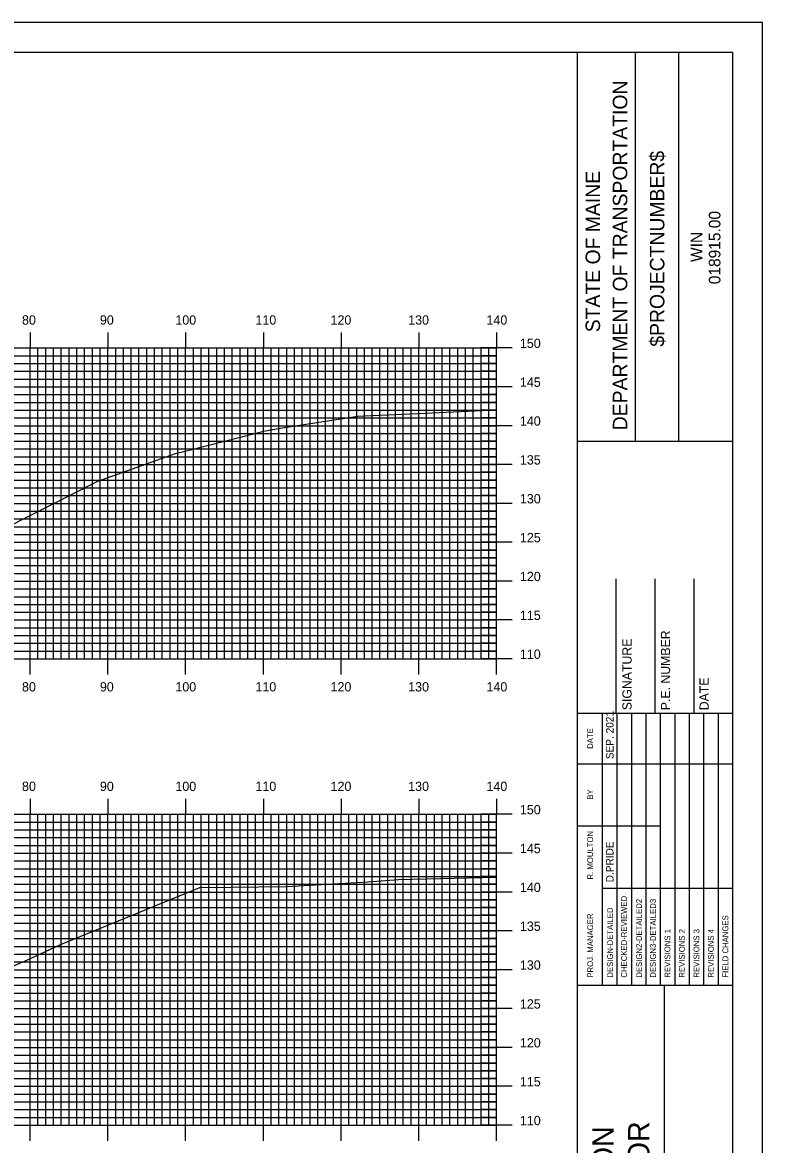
# Model space of a CAD drawing. Extents: x 853721 to 854064, y 364661 to 364881.
# Drawn here: x 853965.8 to 854061, y 364736.9 to 364881.3 of the extents above; entities that cross this region are included whole.
import ezdxf

# ---------------------------------------------------------------- set-up
doc = ezdxf.new("R2010")
doc.units = 0
for name, color, linetype in [('BORDER', 7, 'Continuous'), ('H_V ANNOTATION', 7, 'Continuous'), ('MAJOR', 7, 'Continuous'), ('MINOR', 7, 'Continuous'), ('PLOT BOUNDARY', 7, 'Continuous'), ('S_Roadway_Centerline', 7, 'Continuous')]:
    doc.layers.add(name, color=color, linetype=linetype)

msp = doc.modelspace()

# ---------------------------------------------------------------- linework, layer by layer
at = {"layer": 'BORDER'}
for p, q in [((854037.21, 364667.37), (854037.21, 364877.37)), ((854044.66, 364827.36), (854044.66, 364877.36)), ((854050.25, 364827.36), (854050.25, 364877.36)), ((854037.21, 364827.36), (854057.21, 364827.36)), ((854042.21, 364792.38), (854042.21, 364809.67)), ((854047.21, 364792.38), (854047.21, 364809.67)), ((854052.21, 364792.38), (854052.21, 364809.67)), ((854037.21, 364792.38), (854057.21, 364792.38)), ((854037.21, 364757.38), (854057.21, 364757.38)), ((854048.39, 364687.38), (854048.39, 364757.38))]:
    msp.add_line(p, q, dxfattribs=at)
msp.add_lwpolyline([(853737.21, 364667.37), (854057.21, 364667.37), (854057.21, 364877.37), (853737.21, 364877.37)], close=True, dxfattribs=at)
for points in [[(854040.44, 364785.88), (854040.44, 364792.38)], [(854042.3, 364757.38), (854042.3, 364792.38)], [(854044.17, 364792.38), (854044.17, 364757.38)], [(854046.03, 364757.38), (854046.03, 364792.38)], [(854047.89, 364757.38), (854047.89, 364792.38)], [(854049.76, 364757.38), (854049.76, 364792.38)], [(854051.62, 364757.38), (854051.62, 364792.38)], [(854053.48, 364757.38), (854053.48, 364792.38)], [(854055.35, 364757.38), (854055.35, 364792.38)], [(854040.44, 364757.38), (854040.44, 364790.96)], [(854037.21, 364785.88), (854057.21, 364785.88)], [(854037.21, 364777.88), (854040.44, 364777.88)], [(854040.44, 364777.88), (854047.89, 364777.88)], [(854040.44, 364769.88), (854057.21, 364769.88)]]:
    msp.add_lwpolyline(points, dxfattribs=at)
at = {"layer": 'MAJOR'}
for p, q in [((853966.81, 364841.37), (853966.81, 364839.37)), ((853976.81, 364841.37), (853976.81, 364839.37)), ((853986.81, 364841.37), (853986.81, 364839.37)), ((853996.81, 364841.37), (853996.81, 364839.37)), ((854006.81, 364841.37), (854006.81, 364839.37)), ((854016.81, 364841.37), (854016.81, 364839.37)), ((854026.81, 364841.37), (854026.81, 364839.37)), ((853746.81, 364839.37), (854026.81, 364839.37)), ((853746.81, 364839.37), (854026.81, 364839.37)), ((853966.81, 364799.37), (853966.81, 364839.37)), ((853976.81, 364799.37), (853976.81, 364839.37)), ((853986.81, 364799.37), (853986.81, 364839.37)), ((853996.81, 364799.37), (853996.81, 364839.37)), ((854006.81, 364799.37), (854006.81, 364839.37)), ((854016.81, 364799.37), (854016.81, 364839.37)), ((854028.81, 364839.37), (854024.8, 364839.37)), ((854026.81, 364799.37), (854026.81, 364839.37)), ((854026.81, 364799.37), (854026.81, 364839.37)), ((853746.81, 364834.37), (854026.81, 364834.37)), ((854028.81, 364834.37), (854024.8, 364834.37)), ((853746.81, 364829.37), (854026.81, 364829.37)), ((854028.81, 364829.37), (854024.8, 364829.37)), ((853746.81, 364824.37), (854026.81, 364824.37)), ((854028.81, 364824.37), (854024.8, 364824.37)), ((853746.81, 364819.37), (854026.81, 364819.37)), ((854028.81, 364819.37), (854024.8, 364819.37)), ((853746.81, 364814.37), (854026.81, 364814.37)), ((854028.81, 364814.37), (854024.8, 364814.37)), ((853746.81, 364809.37), (854026.81, 364809.37)), ((854028.81, 364809.37), (854024.8, 364809.37)), ((853746.81, 364804.37), (854026.81, 364804.37)), ((854028.81, 364804.37), (854024.8, 364804.37)), ((853746.81, 364799.37), (854026.81, 364799.37)), ((853746.81, 364799.37), (854026.81, 364799.37)), ((853966.81, 364797.37), (853966.81, 364799.37)), ((853976.81, 364797.37), (853976.81, 364799.37)), ((853986.81, 364797.37), (853986.81, 364799.37)), ((853996.81, 364797.37), (853996.81, 364799.37)), ((854006.81, 364797.37), (854006.81, 364799.37)), ((854016.81, 364797.37), (854016.81, 364799.37)), ((854028.81, 364799.37), (854024.8, 364799.37)), ((854026.81, 364797.37), (854026.81, 364799.37)), ((853966.81, 364781.37), (853966.81, 364779.37)), ((853976.81, 364781.37), (853976.81, 364779.37)), ((853986.81, 364781.37), (853986.81, 364779.37)), ((853996.81, 364781.37), (853996.81, 364779.37)), ((854006.81, 364781.37), (854006.81, 364779.37)), ((854016.81, 364781.37), (854016.81, 364779.37)), ((854026.81, 364781.37), (854026.81, 364779.37)), ((853746.81, 364779.37), (854026.81, 364779.37)), ((853746.81, 364779.37), (854026.81, 364779.37)), ((853966.81, 364739.37), (853966.81, 364779.37)), ((853976.81, 364739.37), (853976.81, 364779.37)), ((853986.81, 364739.37), (853986.81, 364779.37)), ((853996.81, 364739.37), (853996.81, 364779.37)), ((854006.81, 364739.37), (854006.81, 364779.37)), ((854016.81, 364739.37), (854016.81, 364779.37)), ((854028.81, 364779.37), (854024.8, 364779.37)), ((854026.81, 364739.37), (854026.81, 364779.37)), ((854026.81, 364739.37), (854026.81, 364779.37)), ((853746.81, 364774.37), (854026.81, 364774.37)), ((854028.81, 364774.37), (854024.8, 364774.37)), ((853746.81, 364769.37), (854026.81, 364769.37)), ((854028.81, 364769.37), (854024.8, 364769.37)), ((853746.81, 364764.37), (854026.81, 364764.37)), ((854028.81, 364764.37), (854024.8, 364764.37)), ((853746.81, 364759.37), (854026.81, 364759.37)), ((854028.81, 364759.37), (854024.8, 364759.37)), ((853746.81, 364754.37), (854026.81, 364754.37)), ((854028.81, 364754.37), (854024.8, 364754.37)), ((853746.81, 364749.37), (854026.81, 364749.37)), ((854028.81, 364749.37), (854024.8, 364749.37)), ((853746.81, 364744.37), (854026.81, 364744.37)), ((854028.81, 364744.37), (854024.8, 364744.37)), ((853746.81, 364739.37), (854026.81, 364739.37)), ((853746.81, 364739.37), (854026.81, 364739.37)), ((853966.81, 364737.37), (853966.81, 364739.37)), ((853976.81, 364737.37), (853976.81, 364739.37)), ((853986.81, 364737.37), (853986.81, 364739.37)), ((853996.81, 364737.37), (853996.81, 364739.37)), ((854006.81, 364737.37), (854006.81, 364739.37)), ((854016.81, 364737.37), (854016.81, 364739.37)), ((854028.81, 364739.37), (854024.8, 364739.37)), ((854026.81, 364737.37), (854026.81, 364739.37))]:
    msp.add_line(p, q, dxfattribs=at)
at = {"layer": 'MINOR'}
for p, q in [((853746.81, 364838.37), (854026.81, 364838.37)), ((853967.81, 364799.37), (853967.81, 364839.37)), ((853968.81, 364799.37), (853968.81, 364839.37)), ((853969.81, 364799.37), (853969.81, 364839.37)), ((853970.81, 364799.37), (853970.81, 364839.37)), ((853971.81, 364799.37), (853971.81, 364839.37)), ((853972.81, 364799.37), (853972.81, 364839.37)), ((853973.81, 364799.37), (853973.81, 364839.37)), ((853974.81, 364799.37), (853974.81, 364839.37)), ((853975.81, 364799.37), (853975.81, 364839.37)), ((853977.81, 364799.37), (853977.81, 364839.37)), ((853978.81, 364799.37), (853978.81, 364839.37)), ((853979.81, 364799.37), (853979.81, 364839.37)), ((853980.81, 364799.37), (853980.81, 364839.37)), ((853981.81, 364799.37), (853981.81, 364839.37)), ((853982.81, 364799.37), (853982.81, 364839.37)), ((853983.81, 364799.37), (853983.81, 364839.37)), ((853984.81, 364799.37), (853984.81, 364839.37)), ((853985.81, 364799.37), (853985.81, 364839.37)), ((853987.81, 364799.37), (853987.81, 364839.37)), ((853988.81, 364799.37), (853988.81, 364839.37)), ((853989.81, 364799.37), (853989.81, 364839.37)), ((853990.81, 364799.37), (853990.81, 364839.37)), ((853991.81, 364799.37), (853991.81, 364839.37)), ((853992.81, 364799.37), (853992.81, 364839.37)), ((853993.81, 364799.37), (853993.81, 364839.37)), ((853994.81, 364799.37), (853994.81, 364839.37)), ((853995.81, 364799.37), (853995.81, 364839.37)), ((853997.81, 364799.37), (853997.81, 364839.37)), ((853998.81, 364799.37), (853998.81, 364839.37)), ((853999.81, 364799.37), (853999.81, 364839.37)), ((854000.81, 364799.37), (854000.81, 364839.37)), ((854001.81, 364799.37), (854001.81, 364839.37)), ((854002.81, 364799.37), (854002.81, 364839.37)), ((854003.81, 364799.37), (854003.81, 364839.37)), ((854004.81, 364799.37), (854004.81, 364839.37)), ((854005.81, 364799.37), (854005.81, 364839.37)), ((854007.81, 364799.37), (854007.81, 364839.37)), ((854008.81, 364799.37), (854008.81, 364839.37)), ((854009.81, 364799.37), (854009.81, 364839.37)), ((854010.81, 364799.37), (854010.81, 364839.37)), ((854011.81, 364799.37), (854011.81, 364839.37)), ((854012.81, 364799.37), (854012.81, 364839.37)), ((854013.81, 364799.37), (854013.81, 364839.37)), ((854014.81, 364799.37), (854014.81, 364839.37)), ((854015.81, 364799.37), (854015.81, 364839.37)), ((854017.81, 364799.37), (854017.81, 364839.37)), ((854018.81, 364799.37), (854018.81, 364839.37)), ((854019.81, 364799.37), (854019.81, 364839.37)), ((854020.81, 364799.37), (854020.81, 364839.37)), ((854021.81, 364799.37), (854021.81, 364839.37)), ((854022.81, 364799.37), (854022.81, 364839.37)), ((854023.81, 364799.37), (854023.81, 364839.37)), ((854026.81, 364838.37), (854024.8, 364838.37)), ((854024.81, 364799.37), (854024.81, 364839.37)), ((854025.81, 364799.37), (854025.81, 364839.37)), ((853746.81, 364837.37), (854026.81, 364837.37)), ((854026.81, 364837.37), (854024.8, 364837.37)), ((853746.81, 364836.37), (854026.81, 364836.37)), ((853746.81, 364835.37), (854026.81, 364835.37)), ((854026.81, 364836.37), (854024.8, 364836.37)), ((854026.81, 364835.37), (854024.8, 364835.37)), ((853746.81, 364833.37), (854026.81, 364833.37)), ((853746.81, 364832.37), (854026.81, 364832.37)), ((854026.81, 364833.37), (854024.8, 364833.37)), ((854026.81, 364832.37), (854024.8, 364832.37)), ((853746.81, 364831.37), (854026.81, 364831.37)), ((854026.81, 364831.37), (854024.8, 364831.37)), ((853746.81, 364830.37), (854026.81, 364830.37)), ((854026.81, 364830.37), (854024.8, 364830.37)), ((853746.81, 364828.37), (854026.81, 364828.37)), ((854026.81, 364828.37), (854024.8, 364828.37)), ((853746.81, 364827.37), (854026.81, 364827.37)), ((854026.81, 364827.37), (854024.8, 364827.37)), ((853746.81, 364826.37), (854026.81, 364826.37)), ((853746.81, 364825.37), (854026.81, 364825.37)), ((854026.81, 364826.37), (854024.8, 364826.37)), ((854026.81, 364825.37), (854024.8, 364825.37)), ((853746.81, 364823.37), (854026.81, 364823.37)), ((853746.81, 364822.37), (854026.81, 364822.37)), ((854026.81, 364823.37), (854024.8, 364823.37)), ((854026.81, 364822.37), (854024.8, 364822.37)), ((853746.81, 364821.37), (854026.81, 364821.37)), ((854026.81, 364821.37), (854024.8, 364821.37)), ((853746.81, 364820.37), (854026.81, 364820.37)), ((854026.81, 364820.37), (854024.8, 364820.37)), ((853746.81, 364818.37), (854026.81, 364818.37)), ((854026.81, 364818.37), (854024.8, 364818.37)), ((853746.81, 364817.37), (854026.81, 364817.37)), ((853746.81, 364816.37), (854026.81, 364816.37)), ((854026.81, 364817.37), (854024.8, 364817.37)), ((854026.81, 364816.37), (854024.8, 364816.37)), ((853746.81, 364815.37), (854026.81, 364815.37)), ((854026.81, 364815.37), (854024.8, 364815.37)), ((853746.81, 364813.37), (854026.81, 364813.37)), ((853746.81, 364812.37), (854026.81, 364812.37)), ((854026.81, 364813.37), (854024.8, 364813.37)), ((854026.81, 364812.37), (854024.8, 364812.37)), ((853746.81, 364811.37), (854026.81, 364811.37)), ((854026.81, 364811.37), (854024.8, 364811.37)), ((853746.81, 364810.37), (854026.81, 364810.37)), ((854026.81, 364810.37), (854024.8, 364810.37)), ((853746.81, 364808.37), (854026.81, 364808.37)), ((854026.81, 364808.37), (854024.8, 364808.37)), ((853746.81, 364807.37), (854026.81, 364807.37)), ((853746.81, 364806.37), (854026.81, 364806.37)), ((854026.81, 364807.37), (854024.8, 364807.37)), ((854026.81, 364806.37), (854024.8, 364806.37)), ((853746.81, 364805.37), (854026.81, 364805.37)), ((854026.81, 364805.37), (854024.8, 364805.37)), ((853746.81, 364803.37), (854026.81, 364803.37)), ((854026.81, 364803.37), (854024.8, 364803.37)), ((853746.81, 364802.37), (854026.81, 364802.37)), ((854026.81, 364802.37), (854024.8, 364802.37)), ((853746.81, 364801.37), (854026.81, 364801.37)), ((854026.81, 364801.37), (854024.8, 364801.37)), ((853746.81, 364800.37), (854026.81, 364800.37)), ((854026.81, 364800.37), (854024.8, 364800.37)), ((853967.81, 364739.37), (853967.81, 364779.37)), ((853968.81, 364739.37), (853968.81, 364779.37)), ((853969.81, 364739.37), (853969.81, 364779.37)), ((853970.81, 364739.37), (853970.81, 364779.37)), ((853971.81, 364739.37), (853971.81, 364779.37)), ((853972.81, 364739.37), (853972.81, 364779.37)), ((853973.81, 364739.37), (853973.81, 364779.37)), ((853974.81, 364739.37), (853974.81, 364779.37)), ((853975.81, 364739.37), (853975.81, 364779.37)), ((853977.81, 364739.37), (853977.81, 364779.37)), ((853978.81, 364739.37), (853978.81, 364779.37)), ((853979.81, 364739.37), (853979.81, 364779.37)), ((853980.81, 364739.37), (853980.81, 364779.37)), ((853981.81, 364739.37), (853981.81, 364779.37)), ((853982.81, 364739.37), (853982.81, 364779.37)), ((853983.81, 364739.37), (853983.81, 364779.37)), ((853984.81, 364739.37), (853984.81, 364779.37)), ((853985.81, 364739.37), (853985.81, 364779.37)), ((853987.81, 364739.37), (853987.81, 364779.37)), ((853988.81, 364739.37), (853988.81, 364779.37)), ((853989.81, 364739.37), (853989.81, 364779.37)), ((853990.81, 364739.37), (853990.81, 364779.37)), ((853991.81, 364739.37), (853991.81, 364779.37)), ((853992.81, 364739.37), (853992.81, 364779.37)), ((853993.81, 364739.37), (853993.81, 364779.37)), ((853994.81, 364739.37), (853994.81, 364779.37)), ((853995.81, 364739.37), (853995.81, 364779.37)), ((853997.81, 364739.37), (853997.81, 364779.37)), ((853998.81, 364739.37), (853998.81, 364779.37)), ((853999.81, 364739.37), (853999.81, 364779.37)), ((854000.81, 364739.37), (854000.81, 364779.37)), ((854001.81, 364739.37), (854001.81, 364779.37)), ((854002.81, 364739.37), (854002.81, 364779.37)), ((854003.81, 364739.37), (854003.81, 364779.37)), ((854004.81, 364739.37), (854004.81, 364779.37)), ((854005.81, 364739.37), (854005.81, 364779.37)), ((854007.81, 364739.37), (854007.81, 364779.37)), ((854008.81, 364739.37), (854008.81, 364779.37)), ((854009.81, 364739.37), (854009.81, 364779.37)), ((854010.81, 364739.37), (854010.81, 364779.37)), ((854011.81, 364739.37), (854011.81, 364779.37)), ((854012.81, 364739.37), (854012.81, 364779.37)), ((854013.81, 364739.37), (854013.81, 364779.37)), ((854014.81, 364739.37), (854014.81, 364779.37)), ((854015.81, 364739.37), (854015.81, 364779.37)), ((854017.81, 364739.37), (854017.81, 364779.37)), ((854018.81, 364739.37), (854018.81, 364779.37)), ((854019.81, 364739.37), (854019.81, 364779.37)), ((854020.81, 364739.37), (854020.81, 364779.37)), ((854021.81, 364739.37), (854021.81, 364779.37)), ((854022.81, 364739.37), (854022.81, 364779.37)), ((854023.81, 364739.37), (854023.81, 364779.37)), ((854024.81, 364739.37), (854024.81, 364779.37)), ((854025.81, 364739.37), (854025.81, 364779.37)), ((853746.81, 364778.37), (854026.81, 364778.37)), ((853746.81, 364777.37), (854026.81, 364777.37)), ((854026.81, 364778.37), (854024.8, 364778.37)), ((854026.81, 364777.37), (854024.8, 364777.37)), ((853746.81, 364776.37), (854026.81, 364776.37)), ((854026.81, 364776.37), (854024.8, 364776.37)), ((853746.81, 364775.37), (854026.81, 364775.37)), ((854026.81, 364775.37), (854024.8, 364775.37)), ((853746.81, 364773.37), (854026.81, 364773.37)), ((854026.81, 364773.37), (854024.8, 364773.37)), ((853746.81, 364772.37), (854026.81, 364772.37)), ((854026.81, 364772.37), (854024.8, 364772.37)), ((853746.81, 364771.37), (854026.81, 364771.37)), ((853746.81, 364770.37), (854026.81, 364770.37)), ((854026.81, 364771.37), (854024.8, 364771.37)), ((854026.81, 364770.37), (854024.8, 364770.37)), ((853746.81, 364768.37), (854026.81, 364768.37)), ((853746.81, 364767.37), (854026.81, 364767.37)), ((854026.81, 364768.37), (854024.8, 364768.37)), ((854026.81, 364767.37), (854024.8, 364767.37)), ((853746.81, 364766.37), (854026.81, 364766.37)), ((854026.81, 364766.37), (854024.8, 364766.37)), ((853746.81, 364765.37), (854026.81, 364765.37)), ((854026.81, 364765.37), (854024.8, 364765.37)), ((853746.81, 364763.37), (854026.81, 364763.37)), ((854026.81, 364763.37), (854024.8, 364763.37)), ((853746.81, 364762.37), (854026.81, 364762.37)), ((854026.81, 364762.37), (854024.8, 364762.37)), ((853746.81, 364761.37), (854026.81, 364761.37)), ((853746.81, 364760.37), (854026.81, 364760.37)), ((854026.81, 364761.37), (854024.8, 364761.37)), ((854026.81, 364760.37), (854024.8, 364760.37)), ((853746.81, 364758.37), (854026.81, 364758.37)), ((853746.81, 364757.37), (854026.81, 364757.37)), ((854026.81, 364758.37), (854024.8, 364758.37)), ((854026.81, 364757.37), (854024.8, 364757.37)), ((853746.81, 364756.37), (854026.81, 364756.37)), ((854026.81, 364756.37), (854024.8, 364756.37)), ((853746.81, 364755.37), (854026.81, 364755.37)), ((854026.81, 364755.37), (854024.8, 364755.37)), ((853746.81, 364753.37), (854026.81, 364753.37)), ((854026.81, 364753.37), (854024.8, 364753.37)), ((853746.81, 364752.37), (854026.81, 364752.37)), ((853746.81, 364751.37), (854026.81, 364751.37)), ((854026.81, 364752.37), (854024.8, 364752.37)), ((854026.81, 364751.37), (854024.8, 364751.37)), ((853746.81, 364750.37), (854026.81, 364750.37)), ((854026.81, 364750.37), (854024.8, 364750.37)), ((853746.81, 364748.37), (854026.81, 364748.37)), ((853746.81, 364747.37), (854026.81, 364747.37)), ((854026.81, 364748.37), (854024.8, 364748.37)), ((854026.81, 364747.37), (854024.8, 364747.37)), ((853746.81, 364746.37), (854026.81, 364746.37)), ((854026.81, 364746.37), (854024.8, 364746.37)), ((853746.81, 364745.37), (854026.81, 364745.37)), ((854026.81, 364745.37), (854024.8, 364745.37)), ((853746.81, 364743.37), (854026.81, 364743.37)), ((854026.81, 364743.37), (854024.8, 364743.37)), ((853746.81, 364742.37), (854026.81, 364742.37)), ((853746.81, 364741.37), (854026.81, 364741.37)), ((854026.81, 364742.37), (854024.8, 364742.37)), ((854026.81, 364741.37), (854024.8, 364741.37)), ((853746.81, 364740.37), (854026.81, 364740.37)), ((854026.81, 364740.37), (854024.8, 364740.37))]:
    msp.add_line(p, q, dxfattribs=at)
at = {"layer": 'PLOT BOUNDARY'}
msp.add_lwpolyline([(853721.02, 364661.25), (854061.02, 364661.25), (854061.02, 364881.25), (853721.02, 364881.25)], close=True, dxfattribs=at)
at = {"layer": 'S_Roadway_Centerline'}
for points in [[(853963.69, 364816.23), (853975.51, 364822.23), (853985.5, 364825.77), (853986.92, 364826.15), (853996.85, 364828.67), (853998.97, 364829.07), (854008.97, 364830.6), (854017.58, 364830.98), (854026.81, 364831.41)], [(853955.69, 364756.08), (853966.28, 364760.55), (853970.62, 364762.59), (853988.63, 364769.96), (853992.63, 364770.01), (853999.79, 364770.06), (854010.3, 364770.7), (854014.17, 364770.97), (854026.81, 364771.26)]]:
    msp.add_lwpolyline(points, dxfattribs=at)

# ---------------------------------------------------------------- texts
at = {"layer": 'BORDER'}
for s, height, p in [('DEPARTMENT OF TRANSPORTATION', 1.8635, (854043.62, 364828.78)), ('$PROJECTNUMBER$', 1.8635, (854048.39, 364839.53)), ('STATE OF MAINE', 1.8635, (854040.12, 364841.39)), ('018915.00', 1.491, (854055.6, 364847.57)), ('WIN', 1.491, (854053.28, 364850.43)), ('SIGNATURE', 1.181, (854044.17, 364792.76)), ('P.E. NUMBER', 1.1811, (854049.13, 364792.76)), ('DATE', 1.181, (854054.09, 364792.76)), ('SEP. 2021', 0.969, (854041.85, 364786.47)), ('DATE', 0.743, (854039.22, 364787.79)), ('BY', 0.743, (854039.22, 364781.25)), ('R. MOULTON', 0.745, (854039.22, 364770.98)), ('D.PRIDE', 0.969, (854041.85, 364770.62)), ('CHECKED-REVIEWED', 0.7455, (854043.57, 364758.35)), ('DESIGN-DETAILED', 0.7455, (854041.78, 364758.35)), ('DESIGN2-DETAILED2', 0.7455, (854045.51, 364758.35)), ('DESIGN3-DETAILED3', 0.7455, (854047.3, 364758.35)), ('PROJ. MANAGER', 0.7455, (854039.22, 364758.35)), ('FIELD CHANGES', 0.7455, (854056.61, 364758.35)), ('REVISIONS 1', 0.7455, (854049.16, 364758.35)), ('REVISIONS 2', 0.7455, (854051.02, 364758.35)), ('REVISIONS 3', 0.7455, (854052.89, 364758.35)), ('REVISIONS 4', 0.7455, (854054.75, 364758.35)), ('BREWER TO EDDINGTON', 2.7557, (854041.88, 364693.78)), ('I-395/ROUTE 9 CONNECTOR', 2.7557, (854046.47, 364689.7))]:
    msp.add_text(s, height=height, rotation=90, dxfattribs=at).set_placement(p)
at = {"layer": 'H_V ANNOTATION'}
for s, p in [('80', (853965.76, 364842.37)), ('90', (853975.78, 364842.37)), ('100', (853985.49, 364842.37)), ('110', (853995.79, 364842.37)), ('120', (854005.45, 364842.37)), ('130', (854015.44, 364842.37)), ('140', (854025.51, 364842.37)), ('150', (854029.81, 364839.37)), ('145', (854029.81, 364834.37)), ('140', (854029.81, 364829.37)), ('135', (854029.81, 364824.37)), ('130', (854029.81, 364819.37)), ('125', (854029.81, 364814.37)), ('120', (854029.81, 364809.37)), ('115', (854029.81, 364804.37)), ('110', (854029.81, 364799.37)), ('80', (853965.76, 364795.17)), ('90', (853975.78, 364795.17)), ('100', (853985.49, 364795.17)), ('110', (853995.79, 364795.17)), ('120', (854005.45, 364795.17)), ('130', (854015.44, 364795.17)), ('140', (854025.51, 364795.17)), ('80', (853965.76, 364782.37)), ('90', (853975.78, 364782.37)), ('100', (853985.49, 364782.37)), ('110', (853995.79, 364782.37)), ('120', (854005.45, 364782.37)), ('130', (854015.44, 364782.37)), ('140', (854025.51, 364782.37)), ('150', (854029.81, 364779.37)), ('145', (854029.81, 364774.37)), ('140', (854029.81, 364769.37)), ('135', (854029.81, 364764.37)), ('130', (854029.81, 364759.37)), ('125', (854029.81, 364754.37)), ('120', (854029.81, 364749.37)), ('115', (854029.81, 364744.37)), ('110', (854029.81, 364739.37))]:
    msp.add_text(s, height=1.2, dxfattribs=at).set_placement(p)

doc.saveas('drawing.dxf')
